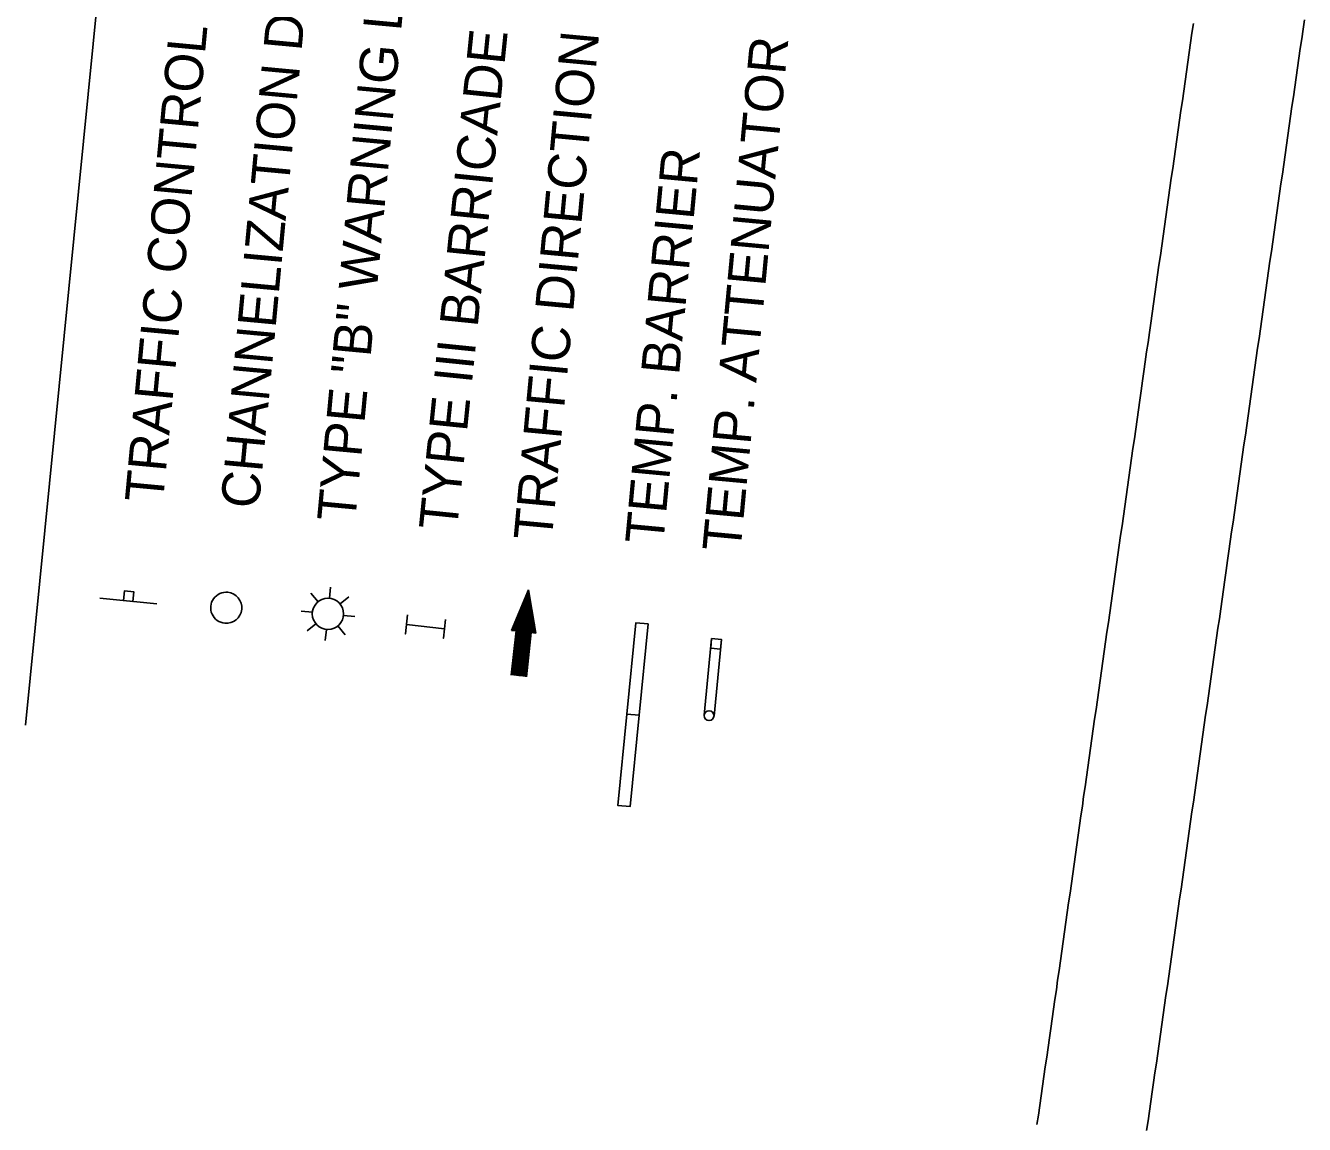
# Model space of a CAD drawing. Extents: x 1795987 to 1799689, y 243690 to 251545.
# Drawn here: x 1797261.4 to 1797522.5, y 247088.9 to 247313.4 of the extents above; entities that cross this region are included whole.
import ezdxf

# ---------------------------------------------------------------- set-up
doc = ezdxf.new("R2010")
doc.units = 0
for name, color, linetype in [('LEGEND', 7, 'Continuous'), ('Level 2', 7, 'Continuous'), ('Level 62', 7, 'Continuous')]:
    doc.layers.add(name, color=color, linetype=linetype)

# ---------------------------------------------------------------- blocks, each defined once
blk = doc.blocks.new('T21LR')
at = {"layer": 'Level 2'}
for p, q in [((0, 2), (31.5, 2)), ((0, -2), (31.5, -2))]:
    blk.add_line(p, q, dxfattribs=at)
blk.add_lwpolyline([(0, -2), (4, -2), (4, 2), (0, 2)], close=True, dxfattribs=at)
blk.add_circle((31.5, 0), 2, dxfattribs=at)

msp = doc.modelspace()

# ---------------------------------------------------------------- linework, layer by layer
at = {"layer": 'LEGEND'}
for p, q in [((1797261.35, 247170.53), (1797308.29, 247644.28)), ((1797321.07, 247195.7), (1797319.61, 247197.49)), ((1797323.41, 247196.41), (1797323.64, 247198.71)), ((1797327.36, 247196.72), (1797325.57, 247195.26)), ((1797364.05, 247198.17), (1797360.6, 247189.86)), ((1797365.57, 247189.3), (1797364.05, 247198.17)), ((1797288.14, 247195.31), (1797276.49, 247196.46)), ((1797319.92, 247193.55), (1797317.62, 247193.78)), ((1797326.28, 247192.92), (1797328.58, 247192.69)), ((1797318.84, 247189.74), (1797320.63, 247191.21)), ((1797322.78, 247190.06), (1797322.55, 247187.76)), ((1797326.59, 247188.98), (1797325.12, 247190.76)), ((1797361.53, 247189.75), (1797360.52, 247180.73)), ((1797360.6, 247189.86), (1797361.53, 247189.75)), ((1797363.62, 247180.38), (1797364.63, 247189.4)), ((1797364.63, 247189.4), (1797365.57, 247189.3))]:
    msp.add_line(p, q, dxfattribs=at)
for points in [[(1797281.34, 247195.98), (1797281.54, 247197.92), (1797283.48, 247197.73), (1797283.28, 247195.79)], [(1797388.47, 247191.18), (1797385.98, 247191.42), (1797384.14, 247172.76), (1797386.63, 247172.52)], [(1797386.63, 247172.52), (1797384.14, 247172.76), (1797382.29, 247154.11), (1797384.78, 247153.86)]]:
    msp.add_lwpolyline(points, close=True, dxfattribs=at)
for points in [[(1797363.56, 247196.99), (1797361.71, 247180.59)], [(1797363.91, 247197.85), (1797361.97, 247180.56)], [(1797364.15, 247197.6), (1797362.23, 247180.53)], [(1797364.31, 247196.68), (1797362.49, 247180.5)], [(1797362.48, 247194.39), (1797360.94, 247180.68)], [(1797362.84, 247195.26), (1797361.2, 247180.65)], [(1797363.2, 247196.12), (1797361.45, 247180.62)], [(1797364.46, 247195.75), (1797362.75, 247180.48)], [(1797364.62, 247194.83), (1797363, 247180.45)], [(1797364.78, 247193.91), (1797363.26, 247180.42)], [(1797347.12, 247192.11), (1797346.67, 247188.24), (1797346.89, 247190.18), (1797339.14, 247191.08), (1797338.92, 247189.14), (1797339.37, 247193.01)], [(1797362.12, 247193.53), (1797360.68, 247180.71)], [(1797361.4, 247191.8), (1797361.18, 247189.79)], [(1797361.76, 247192.67), (1797361.44, 247189.76)], [(1797364.94, 247192.99), (1797363.52, 247180.39)], [(1797365.1, 247192.06), (1797364.79, 247189.38)], [(1797360.69, 247190.07), (1797360.66, 247189.85)], [(1797361.04, 247190.94), (1797360.92, 247189.82)], [(1797365.25, 247191.14), (1797365.05, 247189.35)], [(1797365.41, 247190.22), (1797365.31, 247189.33)]]:
    msp.add_lwpolyline(points, dxfattribs=at)
msp.add_circle((1797323.1, 247193.23), 3.19, dxfattribs=at)
for start, end in [(84.3414, 264.3414), (264.3414, 84.3414)]:
    msp.add_arc((1797302.33, 247194.48), 3.18, start, end, dxfattribs=at)
at = {"layer": 'Level 62'}
for points in [[(1797522.5, 247314.6), (1797522.22, 247312.63), (1797521.94, 247310.66), (1797521.65, 247308.68), (1797521.37, 247306.71), (1797521.09, 247304.74), (1797520.81, 247302.77), (1797520.53, 247300.79), (1797520.25, 247298.82), (1797519.96, 247296.85), (1797519.68, 247294.88), (1797519.4, 247292.9), (1797519.12, 247290.93), (1797518.84, 247288.96), (1797518.56, 247286.99), (1797518.28, 247285.01), (1797517.99, 247283.04), (1797517.71, 247281.07), (1797517.43, 247279.1), (1797517.15, 247277.12), (1797516.87, 247275.15), (1797516.59, 247273.18), (1797516.31, 247271.21), (1797516.03, 247269.23), (1797515.75, 247267.26), (1797515.47, 247265.28), (1797515.19, 247263.31), (1797514.91, 247261.34), (1797514.63, 247259.36), (1797514.35, 247257.39), (1797514.07, 247255.41), (1797513.79, 247253.44), (1797513.51, 247251.47), (1797513.23, 247249.49), (1797512.95, 247247.52), (1797512.67, 247245.55), (1797512.39, 247243.57), (1797512.11, 247241.6), (1797511.83, 247239.62), (1797511.55, 247237.65), (1797511.28, 247235.68), (1797511, 247233.7), (1797510.72, 247231.73), (1797510.44, 247229.76), (1797510.16, 247227.78), (1797509.88, 247225.81), (1797509.6, 247223.83), (1797509.32, 247221.86), (1797509.04, 247219.89), (1797508.76, 247217.91), (1797508.48, 247215.94), (1797508.2, 247213.97), (1797507.92, 247211.99), (1797507.64, 247210.02), (1797507.36, 247208.04), (1797507.08, 247206.07), (1797506.8, 247204.1), (1797506.52, 247202.12), (1797506.24, 247200.15), (1797505.96, 247198.18), (1797505.69, 247196.2), (1797505.41, 247194.23), (1797505.13, 247192.25), (1797504.85, 247190.28), (1797504.57, 247188.31), (1797504.29, 247186.33), (1797504.01, 247184.36), (1797503.73, 247182.39), (1797503.45, 247180.41), (1797503.17, 247178.44), (1797502.89, 247176.46), (1797502.61, 247174.49), (1797502.33, 247172.52), (1797502.05, 247170.54), (1797501.77, 247168.57), (1797501.49, 247166.6), (1797501.21, 247164.62), (1797500.93, 247162.65), (1797500.65, 247160.67), (1797500.37, 247158.7), (1797500.1, 247156.73), (1797499.82, 247154.75), (1797499.54, 247152.78), (1797499.26, 247150.8), (1797498.98, 247148.83), (1797498.7, 247146.86), (1797498.42, 247144.88), (1797498.14, 247142.91), (1797497.86, 247140.94), (1797497.58, 247138.96), (1797497.3, 247136.99), (1797497.02, 247135.01), (1797496.74, 247133.04), (1797496.46, 247131.07), (1797496.18, 247129.09), (1797495.9, 247127.12), (1797495.62, 247125.15), (1797495.34, 247123.17), (1797495.06, 247121.2), (1797494.78, 247119.22), (1797494.51, 247117.25), (1797494.23, 247115.28), (1797493.95, 247113.3), (1797493.67, 247111.33), (1797493.39, 247109.36), (1797493.11, 247107.38), (1797492.83, 247105.41), (1797492.55, 247103.44), (1797492.26, 247101.48), (1797491.98, 247099.51), (1797491.7, 247097.54), (1797491.41, 247095.58), (1797491.13, 247093.61), (1797490.85, 247091.65), (1797490.57, 247089.68), (1797490.28, 247087.72)], [(1797490.28, 247087.72), (1797490.57, 247089.68), (1797490.85, 247091.65), (1797491.13, 247093.61), (1797491.41, 247095.58), (1797491.7, 247097.54), (1797491.98, 247099.51), (1797492.26, 247101.48), (1797492.55, 247103.44), (1797492.83, 247105.41), (1797493.11, 247107.38), (1797493.39, 247109.36), (1797493.67, 247111.33), (1797493.95, 247113.3), (1797494.23, 247115.28), (1797494.51, 247117.25), (1797494.78, 247119.22), (1797495.06, 247121.2), (1797495.34, 247123.17), (1797495.62, 247125.15), (1797495.9, 247127.12), (1797496.18, 247129.09), (1797496.46, 247131.07), (1797496.74, 247133.04), (1797497.02, 247135.01), (1797497.3, 247136.99), (1797497.58, 247138.96), (1797497.86, 247140.94), (1797498.14, 247142.91), (1797498.42, 247144.88), (1797498.7, 247146.86), (1797498.98, 247148.83), (1797499.26, 247150.8), (1797499.54, 247152.78), (1797499.82, 247154.75), (1797500.1, 247156.73), (1797500.37, 247158.7), (1797500.65, 247160.67), (1797500.93, 247162.65), (1797501.21, 247164.62), (1797501.49, 247166.6), (1797501.77, 247168.57), (1797502.05, 247170.54), (1797502.33, 247172.52), (1797502.61, 247174.49), (1797502.89, 247176.46), (1797503.17, 247178.44), (1797503.45, 247180.41), (1797503.73, 247182.39), (1797504.01, 247184.36), (1797504.29, 247186.33), (1797504.57, 247188.31), (1797504.85, 247190.28), (1797505.13, 247192.25), (1797505.41, 247194.23), (1797505.69, 247196.2), (1797505.96, 247198.18), (1797506.24, 247200.15), (1797506.52, 247202.12), (1797506.8, 247204.1), (1797507.08, 247206.07), (1797507.36, 247208.04), (1797507.64, 247210.02), (1797507.92, 247211.99), (1797508.2, 247213.97), (1797508.48, 247215.94), (1797508.76, 247217.91), (1797509.04, 247219.89), (1797509.32, 247221.86), (1797509.6, 247223.83), (1797509.88, 247225.81), (1797510.16, 247227.78), (1797510.44, 247229.76), (1797510.72, 247231.73), (1797511, 247233.7), (1797511.28, 247235.68), (1797511.55, 247237.65), (1797511.83, 247239.62), (1797512.11, 247241.6), (1797512.39, 247243.57), (1797512.67, 247245.55), (1797512.95, 247247.52), (1797513.23, 247249.49), (1797513.51, 247251.47), (1797513.79, 247253.44), (1797514.07, 247255.41), (1797514.35, 247257.39), (1797514.63, 247259.36), (1797514.91, 247261.34), (1797515.19, 247263.31), (1797515.47, 247265.28), (1797515.75, 247267.26), (1797516.03, 247269.23), (1797516.31, 247271.21), (1797516.59, 247273.18), (1797516.87, 247275.15), (1797517.15, 247277.12), (1797517.43, 247279.1), (1797517.71, 247281.07), (1797517.99, 247283.04), (1797518.28, 247285.01), (1797518.56, 247286.99), (1797518.84, 247288.96), (1797519.12, 247290.93), (1797519.4, 247292.9), (1797519.68, 247294.88), (1797519.96, 247296.85), (1797520.25, 247298.82), (1797520.53, 247300.79), (1797520.81, 247302.77), (1797521.09, 247304.74), (1797521.37, 247306.71), (1797521.65, 247308.68), (1797521.94, 247310.66), (1797522.22, 247312.63), (1797522.5, 247314.6)], [(1797467.89, 247088.91), (1797468.17, 247090.87), (1797468.45, 247092.84), (1797468.74, 247094.8), (1797469.02, 247096.77), (1797469.3, 247098.73), (1797469.59, 247100.7), (1797469.87, 247102.67), (1797470.15, 247104.63), (1797470.43, 247106.6), (1797470.72, 247108.56), (1797471, 247110.54), (1797471.28, 247112.51), (1797471.56, 247114.49), (1797471.84, 247116.46), (1797472.11, 247118.43), (1797472.39, 247120.41), (1797472.67, 247122.38), (1797472.95, 247124.35), (1797473.23, 247126.33), (1797473.51, 247128.3), (1797473.79, 247130.27), (1797474.07, 247132.25), (1797474.35, 247134.22), (1797474.63, 247136.19), (1797474.91, 247138.17), (1797475.19, 247140.14), (1797475.47, 247142.12), (1797475.75, 247144.09), (1797476.03, 247146.06), (1797476.31, 247148.04), (1797476.59, 247150.01), (1797476.87, 247151.98), (1797477.15, 247153.96), (1797477.42, 247155.93), (1797477.7, 247157.9), (1797477.98, 247159.88), (1797478.26, 247161.85), (1797478.54, 247163.83), (1797478.82, 247165.8), (1797479.1, 247167.77), (1797479.38, 247169.75), (1797479.66, 247171.72), (1797479.94, 247173.69), (1797480.22, 247175.67), (1797480.5, 247177.64), (1797480.78, 247179.61), (1797481.06, 247181.59), (1797481.34, 247183.56), (1797481.62, 247185.54), (1797481.9, 247187.51), (1797482.18, 247189.48), (1797482.46, 247191.46), (1797482.74, 247193.43), (1797483.01, 247195.4), (1797483.29, 247197.38), (1797483.57, 247199.35), (1797483.85, 247201.32), (1797484.13, 247203.3), (1797484.41, 247205.27), (1797484.69, 247207.25), (1797484.97, 247209.22), (1797485.25, 247211.19), (1797485.53, 247213.17), (1797485.81, 247215.14), (1797486.09, 247217.11), (1797486.37, 247219.09), (1797486.65, 247221.06), (1797486.93, 247223.03), (1797487.21, 247225.01), (1797487.49, 247226.98), (1797487.77, 247228.96), (1797488.05, 247230.93), (1797488.32, 247232.9), (1797488.6, 247234.88), (1797488.88, 247236.85), (1797489.16, 247238.82), (1797489.44, 247240.8), (1797489.72, 247242.77), (1797490, 247244.74), (1797490.28, 247246.72), (1797490.56, 247248.69), (1797490.84, 247250.67), (1797491.12, 247252.64), (1797491.4, 247254.61), (1797491.68, 247256.59), (1797491.96, 247258.56), (1797492.24, 247260.53), (1797492.52, 247262.51), (1797492.8, 247264.48), (1797493.08, 247266.45), (1797493.36, 247268.43), (1797493.63, 247270.4), (1797493.91, 247272.38), (1797494.19, 247274.35), (1797494.47, 247276.32), (1797494.76, 247278.3), (1797495.04, 247280.27), (1797495.32, 247282.24), (1797495.6, 247284.21), (1797495.88, 247286.19), (1797496.16, 247288.16), (1797496.44, 247290.13), (1797496.73, 247292.1), (1797497.01, 247294.08), (1797497.29, 247296.05), (1797497.57, 247298.02), (1797497.85, 247300), (1797498.13, 247301.97), (1797498.42, 247303.94), (1797498.7, 247305.91), (1797498.98, 247307.89), (1797499.26, 247309.86), (1797499.54, 247311.83), (1797499.82, 247313.8)], [(1797499.82, 247313.8), (1797499.54, 247311.83), (1797499.26, 247309.86), (1797498.98, 247307.89), (1797498.7, 247305.91), (1797498.42, 247303.94), (1797498.13, 247301.97), (1797497.85, 247300), (1797497.57, 247298.02), (1797497.29, 247296.05), (1797497.01, 247294.08), (1797496.73, 247292.1), (1797496.44, 247290.13), (1797496.16, 247288.16), (1797495.88, 247286.19), (1797495.6, 247284.21), (1797495.32, 247282.24), (1797495.04, 247280.27), (1797494.76, 247278.3), (1797494.47, 247276.32), (1797494.19, 247274.35), (1797493.91, 247272.38), (1797493.63, 247270.4), (1797493.36, 247268.43), (1797493.08, 247266.45), (1797492.8, 247264.48), (1797492.52, 247262.51), (1797492.24, 247260.53), (1797491.96, 247258.56), (1797491.68, 247256.59), (1797491.4, 247254.61), (1797491.12, 247252.64), (1797490.84, 247250.67), (1797490.56, 247248.69), (1797490.28, 247246.72), (1797490, 247244.74), (1797489.72, 247242.77), (1797489.44, 247240.8), (1797489.16, 247238.82), (1797488.88, 247236.85), (1797488.6, 247234.88), (1797488.32, 247232.9), (1797488.05, 247230.93), (1797487.77, 247228.96), (1797487.49, 247226.98), (1797487.21, 247225.01), (1797486.93, 247223.03), (1797486.65, 247221.06), (1797486.37, 247219.09), (1797486.09, 247217.11), (1797485.81, 247215.14), (1797485.53, 247213.17), (1797485.25, 247211.19), (1797484.97, 247209.22), (1797484.69, 247207.25), (1797484.41, 247205.27), (1797484.13, 247203.3), (1797483.85, 247201.32), (1797483.57, 247199.35), (1797483.29, 247197.38), (1797483.01, 247195.4), (1797482.74, 247193.43), (1797482.46, 247191.46), (1797482.18, 247189.48), (1797481.9, 247187.51), (1797481.62, 247185.54), (1797481.34, 247183.56), (1797481.06, 247181.59), (1797480.78, 247179.61), (1797480.5, 247177.64), (1797480.22, 247175.67), (1797479.94, 247173.69), (1797479.66, 247171.72), (1797479.38, 247169.75), (1797479.1, 247167.77), (1797478.82, 247165.8), (1797478.54, 247163.83), (1797478.26, 247161.85), (1797477.98, 247159.88), (1797477.7, 247157.9), (1797477.42, 247155.93), (1797477.15, 247153.96), (1797476.87, 247151.98), (1797476.59, 247150.01), (1797476.31, 247148.04), (1797476.03, 247146.06), (1797475.75, 247144.09), (1797475.47, 247142.12), (1797475.19, 247140.14), (1797474.91, 247138.17), (1797474.63, 247136.19), (1797474.35, 247134.22), (1797474.07, 247132.25), (1797473.79, 247130.27), (1797473.51, 247128.3), (1797473.23, 247126.33), (1797472.95, 247124.35), (1797472.67, 247122.38), (1797472.39, 247120.41), (1797472.11, 247118.43), (1797471.84, 247116.46), (1797471.56, 247114.49), (1797471.28, 247112.51), (1797471, 247110.54), (1797470.72, 247108.56), (1797470.43, 247106.6), (1797470.15, 247104.63), (1797469.87, 247102.67), (1797469.59, 247100.7), (1797469.3, 247098.73), (1797469.02, 247096.77), (1797468.74, 247094.8), (1797468.45, 247092.84), (1797468.17, 247090.87), (1797467.89, 247088.91)]]:
    msp.add_lwpolyline(points, dxfattribs=at)

# ---------------------------------------------------------------- block references
at = {"layer": 'LEGEND', "xscale": 0.5000000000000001, "yscale": 0.5000000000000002, "rotation": -95.50928026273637}
msp.add_blockref('T21LR', (1797402.45, 247188.12), dxfattribs=at)

# ---------------------------------------------------------------- texts
at = {"layer": 'LEGEND'}
for s, rotation, p in [('TYPE "B" WARNING LIGHT', 84.6544, (1797328.64, 247211.85)), ('TRAFFIC CONTROL SIGN', 84.6544, (1797289.39, 247215.75)), ('CHANNELIZATION DRUM', 84.6544, (1797308.94, 247214.55)), ('TYPE III BARRICADE', 84.1754, (1797349.42, 247210.1)), ('TRAFFIC DIRECTION', 84.6544, (1797368.78, 247208.01)), ('TEMP. ATTENUATOR', 84.6544, (1797407.32, 247205.74)), ('TEMP. BARRIER', 84.6544, (1797391.55, 247207.25))]:
    msp.add_text(s, height=7.7999, rotation=rotation, dxfattribs=at).set_placement(p)

doc.saveas('drawing.dxf')
